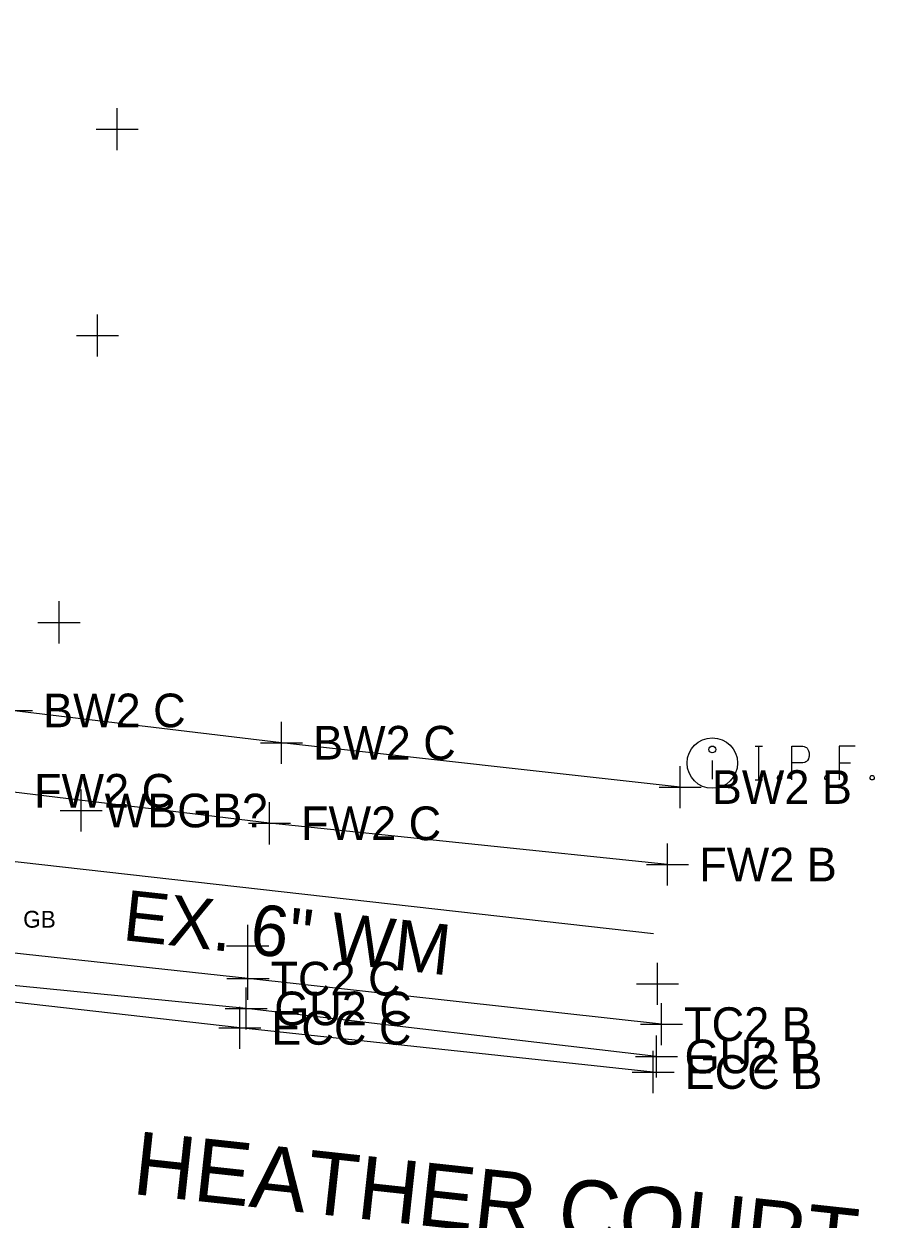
# Model space of a CAD drawing. Extents: x 1363693 to 1365209, y 422201 to 424153.
# Drawn here: x 1364336.2 to 1364376.6, y 423446.2 to 423503 of the extents above; entities that cross this region are included whole.
import ezdxf

# ---------------------------------------------------------------- set-up
doc = ezdxf.new("R2010")
doc.units = 0
for name, color, linetype in [('BASELINE-CL-RW', 7, 'Continuous'), ('O-ALGN-TEXT-BASELINE-WERK-CL-RW', 7, 'Continuous'), ('OWNERS', 7, 'Continuous'), ('PV_X_Driveway', 7, 'Continuous'), ('RD_X_Text', 7, 'Continuous'), ('SV_X_Mon_Cells_Found', 7, 'Continuous'), ('SV_X_Original_Ground', 7, 'Continuous'), ('SV_X_Shot_Marker', 7, 'Continuous'), ('UT_X_Gas_Text', 7, 'Continuous'), ('UT_X_Water', 7, 'Continuous'), ('UT_X_Water_Text', 7, 'Continuous')]:
    doc.layers.add(name, color=color, linetype=linetype)

msp = doc.modelspace()

# ---------------------------------------------------------------- linework, layer by layer
at = {"layer": 'BASELINE-CL-RW'}
msp.add_lwpolyline([(1364366.524, 423455.459), (1364346.875, 423457.621), (1364325.536, 423459.948), (1364322.295, 423460.311), (1364319.345, 423460.588), (1364316.29, 423460.954), (1364315.14, 423461.002), (1364312.666, 423461.468), (1364312.666, 423461.468), (1364311.441, 423461.814), (1364311.441, 423461.814), (1364308.322, 423462.9), (1364308.322, 423462.9), (1364307.878, 423463.057), (1364307.878, 423463.057), (1364307.768, 423463.096), (1364307.768, 423463.096), (1364307.234, 423463.288), (1364307.234, 423463.288), (1364306.159, 423463.76), (1364306.159, 423463.76), (1364304.893, 423464.515), (1364304.893, 423464.515)], dxfattribs=at)
at = {"layer": 'O-ALGN-TEXT-BASELINE-WERK-CL-RW'}
for points in [[(1364367.411, 423466.726), (1364348.47, 423468.833), (1364335.639, 423470.368), (1364320.777, 423472.084), (1364307.678, 423473.708), (1364308.926, 423484.875), (1364311.614, 423510.067), (1364312.676, 423521.008), (1364313.789, 423534.696), (1364316.163, 423559.427)], [(1364366.811, 423463.042), (1364347.898, 423465.004), (1364335.211, 423466.549), (1364320.575, 423468.191), (1364307.721, 423469.627), (1364307.234, 423463.288)]]:
    msp.add_lwpolyline(points, dxfattribs=at)
at = {"layer": 'OWNERS'}
for points in [[(1364366.279, 423453.922), (1364346.787, 423456.205), (1364325.276, 423458.333), (1364322.291, 423459.679)], [(1364366.122, 423453.184), (1364346.486, 423455.281), (1364325.111, 423457.702), (1364321.762, 423458.201)]]:
    msp.add_lwpolyline(points, dxfattribs=at)
at = {"layer": 'PV_X_Driveway'}
for points in [[(1364366.279, 423453.922), (1364346.787, 423456.205), (1364325.276, 423458.333), (1364322.291, 423459.679)], [(1364366.122, 423453.184), (1364346.486, 423455.281), (1364325.111, 423457.702), (1364321.762, 423458.201)]]:
    msp.add_lwpolyline(points, dxfattribs=at)
at = {"layer": 'SV_X_Mon_Cells_Found'}
msp.add_line((1364368.935, 423467.982), (1364368.935, 423467.099), dxfattribs=at)
for points in [[(1364370.966, 423468.666), (1364371.318, 423468.666)], [(1364371.142, 423467.066), (1364371.142, 423468.666)], [(1364372.707, 423467.066), (1364372.707, 423468.666), (1364373.236, 423468.666), (1364373.292, 423468.653), (1364373.369, 423468.628), (1364373.402, 423468.603), (1364373.435, 423468.577), (1364373.479, 423468.515), (1364373.512, 423468.451), (1364373.534, 423468.351), (1364373.534, 423468.199), (1364373.523, 423468.149), (1364373.501, 423468.074), (1364373.457, 423467.985), (1364373.413, 423467.948), (1364373.38, 423467.922), (1364373.325, 423467.897), (1364373.236, 423467.885), (1364372.707, 423467.885)], [(1364375.717, 423468.666), (1364374.956, 423468.666), (1364374.956, 423467.066)], [(1364374.956, 423467.885), (1364375.496, 423467.885)], [(1364370.966, 423467.066), (1364371.318, 423467.066)], [(1364372.101, 423467.28), (1364372.156, 423467.28), (1364372.189, 423467.255), (1364372.222, 423467.204), (1364372.222, 423467.141), (1364372.189, 423467.091), (1364372.156, 423467.066), (1364372.101, 423467.066), (1364372.068, 423467.091), (1364372.035, 423467.141), (1364372.035, 423467.204), (1364372.068, 423467.255), (1364372.101, 423467.28)], [(1364374.35, 423467.28), (1364374.405, 423467.28), (1364374.438, 423467.255), (1364374.471, 423467.204), (1364374.471, 423467.141), (1364374.438, 423467.091), (1364374.405, 423467.066), (1364374.35, 423467.066), (1364374.317, 423467.091), (1364374.284, 423467.141), (1364374.284, 423467.204), (1364374.317, 423467.255), (1364374.35, 423467.28)], [(1364376.499, 423467.28), (1364376.554, 423467.28), (1364376.587, 423467.255), (1364376.62, 423467.204), (1364376.62, 423467.141), (1364376.587, 423467.091), (1364376.554, 423467.066), (1364376.499, 423467.066), (1364376.466, 423467.091), (1364376.433, 423467.141), (1364376.433, 423467.204), (1364376.466, 423467.255), (1364376.499, 423467.28)]]:
    msp.add_lwpolyline(points, dxfattribs=at)
for centre, radius in [((1364368.935, 423467.866), 1.2), ((1364368.935, 423468.517), 0.16)]:
    msp.add_circle(centre, radius, dxfattribs=at)
at = {"layer": 'SV_X_Original_Ground'}
for p, q in [((1364340.657, 423496.994), (1364340.657, 423498.994)), ((1364339.657, 423497.994), (1364341.657, 423497.994)), ((1364339.724, 423487.184), (1364339.724, 423489.184)), ((1364338.724, 423488.184), (1364340.724, 423488.184)), ((1364337.898, 423473.555), (1364337.898, 423475.555)), ((1364336.898, 423474.555), (1364338.898, 423474.555)), ((1364338.949, 423464.611), (1364338.949, 423466.611)), ((1364337.949, 423465.611), (1364339.949, 423465.611)), ((1364346.863, 423458.184), (1364346.863, 423460.184)), ((1364345.863, 423459.184), (1364347.863, 423459.184)), ((1364366.335, 423456.374), (1364366.335, 423458.374)), ((1364365.335, 423457.374), (1364367.335, 423457.374))]:
    msp.add_line(p, q, dxfattribs=at)
at = {"layer": 'SV_X_Shot_Marker'}
for p, q in [((1364334.639, 423470.368), (1364336.639, 423470.368)), ((1364348.47, 423467.833), (1364348.47, 423469.833)), ((1364347.47, 423468.833), (1364349.47, 423468.833)), ((1364367.411, 423465.726), (1364367.411, 423467.726)), ((1364366.411, 423466.726), (1364368.411, 423466.726)), ((1364347.898, 423464.004), (1364347.898, 423466.004)), ((1364346.898, 423465.004), (1364348.898, 423465.004)), ((1364366.811, 423462.042), (1364366.811, 423464.042)), ((1364365.811, 423463.042), (1364367.811, 423463.042)), ((1364346.875, 423456.621), (1364346.875, 423458.621)), ((1364345.875, 423457.621), (1364347.875, 423457.621)), ((1364346.787, 423455.205), (1364346.787, 423457.205)), ((1364346.486, 423454.281), (1364346.486, 423456.281)), ((1364366.524, 423454.459), (1364366.524, 423456.459)), ((1364345.787, 423456.205), (1364347.787, 423456.205)), ((1364345.486, 423455.281), (1364347.486, 423455.281)), ((1364365.524, 423455.459), (1364367.524, 423455.459)), ((1364366.279, 423452.922), (1364366.279, 423454.922)), ((1364366.122, 423452.184), (1364366.122, 423454.184)), ((1364365.279, 423453.922), (1364367.279, 423453.922)), ((1364365.122, 423453.184), (1364367.122, 423453.184))]:
    msp.add_line(p, q, dxfattribs=at)
at = {"layer": 'UT_X_Water'}
msp.add_line((1364295.454, 423467.739), (1364366.137, 423459.762), dxfattribs=at)

# ---------------------------------------------------------------- texts
at = {"layer": 'RD_X_Text'}
msp.add_text('HEATHER COURT', height=3, rotation=353.8084, dxfattribs=at).set_placement((1364341.331, 423447.393))
at = {"layer": 'SV_X_Original_Ground'}
msp.add_text('WBGB?', height=1.6, dxfattribs=at).set_placement((1364340.068, 423464.811))
at = {"layer": 'SV_X_Shot_Marker'}
for s, p in [('BW2 C', (1364337.139, 423469.568)), ('BW2 C', (1364349.97, 423468.033)), ('FW2 C', (1364336.711, 423465.749)), ('BW2 B', (1364368.911, 423465.926)), ('FW2 C', (1364349.398, 423464.204)), ('FW2 B', (1364368.311, 423462.242)), ('TC2 C', (1364347.946, 423456.821)), ('GU2 C', (1364348.124, 423455.405)), ('TC2 B', (1364367.595, 423454.659)), ('ECC C', (1364347.986, 423454.481)), ('GU2 B', (1364367.616, 423453.122)), ('ECC B', (1364367.622, 423452.384))]:
    msp.add_text(s, height=1.6, dxfattribs=at).set_placement(p)
at = {"layer": 'UT_X_Gas_Text'}
msp.add_text('GB', height=0.8, dxfattribs=at).set_placement((1364336.197, 423460.043))
at = {"layer": 'UT_X_Water_Text'}
msp.add_text('EX. 6" WM', height=2.4, rotation=353.8006, dxfattribs=at).set_placement((1364340.873, 423459.458))

doc.saveas('drawing.dxf')
